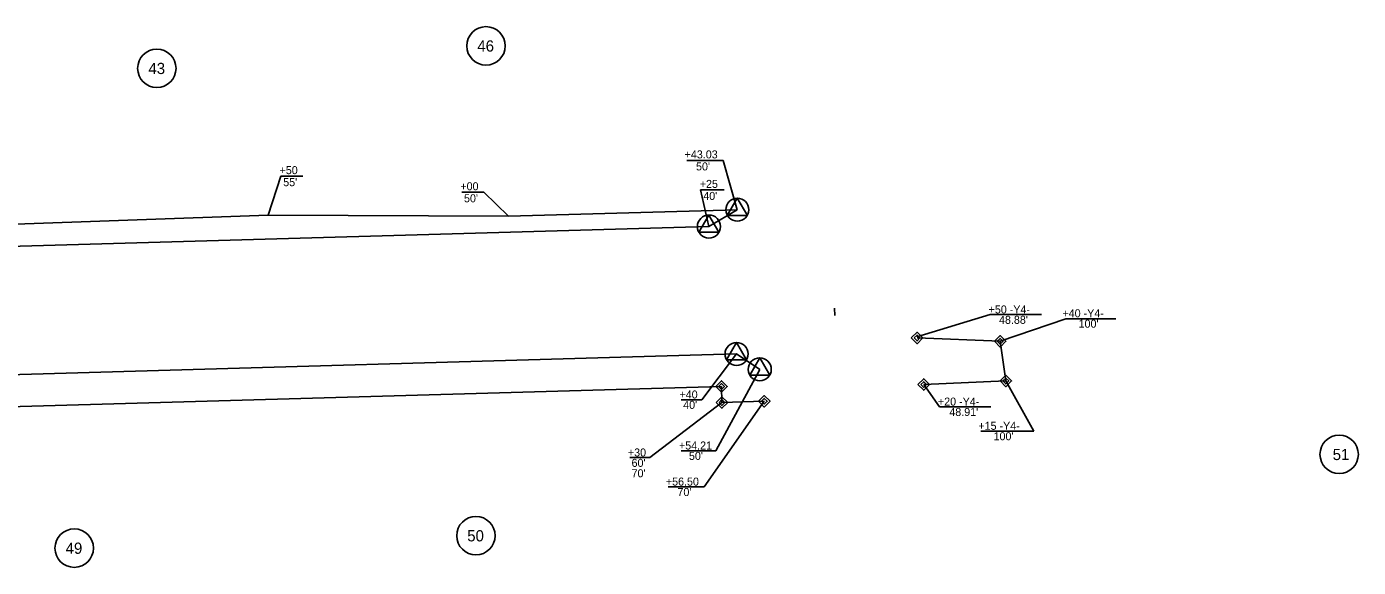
# Model space of a CAD drawing. Extents: x 1756120 to 1760612, y 736784 to 737319.
# Drawn here: x 1759780 to 1760612, y 736882 to 737219 of the extents above; entities that cross this region are included whole.
import ezdxf

# ---------------------------------------------------------------- set-up
doc = ezdxf.new("R2010")
doc.units = 0
for name, color, linetype in [('Prop Easement Construction', 7, 'Continuous'), ('Prop Easement Construction Station Offsets', 7, 'Continuous'), ('Prop Easement Permanent Drainage', 7, 'Continuous'), ('Prop Easement Permanent Drainage Station Offsets', 7, 'Continuous'), ('Prop Easement Permanent Utility', 7, 'Continuous'), ('Prop Easement Permanent Utility Station Offsets', 7, 'Continuous'), ('Prop Easement Temporary Drainage', 7, 'Continuous'), ('Prop Parcel Number CELL', 7, 'Continuous'), ('Prop Parcel Number Text', 7, 'Continuous'), ('Prop ROW Marker CELL', 7, 'Continuous'), ('Prop ROW Permanent Easement CELL', 7, 'Continuous'), ('Prop ROW RW Lines', 7, 'Continuous'), ('Prop ROW Station Offsets', 7, 'Continuous')]:
    doc.layers.add(name, color=color, linetype=linetype)

msp = doc.modelspace()

# ---------------------------------------------------------------- linework, layer by layer
at = {"layer": 'Prop Easement Construction'}
for p, q in [((1760081.35, 737100.66), (1760224.33, 737104.72)), ((1759281.67, 737077.95), (1759931.27, 737101.4)), ((1759931.27, 737101.4), (1760081.35, 737100.66))]:
    msp.add_line(p, q, dxfattribs=at)
at = {"layer": 'Prop Easement Construction Station Offsets'}
for p, q in [((1759939.31, 737125.65), (1759931.27, 737101.4)), ((1759953.03, 737125.65), (1759939.31, 737125.65)), ((1760065.96, 737115.59), (1760052.24, 737115.59)), ((1760065.96, 737115.59), (1760081.35, 737100.66))]:
    msp.add_line(p, q, dxfattribs=at)
at = {"layer": 'Prop Easement Permanent Drainage'}
for p, q in [((1760336.57, 737024.65), (1760388.49, 737022.58)), ((1760392.01, 736997.83), (1760388.49, 737022.58)), ((1760340.72, 736995.59), (1760392.01, 736997.83))]:
    msp.add_line(p, q, dxfattribs=at)
at = {"layer": 'Prop Easement Permanent Drainage Station Offsets'}
for p, q in [((1760336.47, 737025.29), (1760382.24, 737039.22)), ((1760414.34, 737039.22), (1760382.24, 737039.22)), ((1760429.44, 737036.71), (1760388.49, 737022.58)), ((1760460.71, 737036.71), (1760429.44, 737036.71)), ((1760409.51, 736966.46), (1760392.01, 736997.83)), ((1760350.6, 736981.71), (1760340.72, 736995.59)), ((1760382.7, 736981.71), (1760350.6, 736981.71)), ((1760409.51, 736966.46), (1760376.33, 736966.46))]:
    msp.add_line(p, q, dxfattribs=at)
at = {"layer": 'Prop Easement Permanent Utility'}
for p, q in [((1759384.75, 736970.83), (1760214.42, 736994.39)), ((1760214.7, 736984.4), (1760214.42, 736994.39)), ((1760214.7, 736984.4), (1760241.19, 736985.15))]:
    msp.add_line(p, q, dxfattribs=at)
at = {"layer": 'Prop Easement Permanent Utility Station Offsets'}
for p, q in [((1760169.64, 736949.97), (1760214.7, 736984.4)), ((1760203.7, 736931.77), (1760241.19, 736985.15)), ((1760169.64, 736949.97), (1760157.11, 736949.97)), ((1760203.7, 736931.77), (1760181.04, 736931.77))]:
    msp.add_line(p, q, dxfattribs=at)
at = {"layer": 'Prop Easement Temporary Drainage'}
msp.add_line((1760284.96, 737043.18), (1760285.24, 737038.59), dxfattribs=at)
at = {"layer": 'Prop Parcel Number CELL'}
for centre in [(1760067.34, 737206.96), (1759861.77, 737192.94), (1760600.22, 736952.03), (1759810.16, 736893.5), (1760061.06, 736901.26)]:
    msp.add_circle(centre, 12, dxfattribs=at)
at = {"layer": 'Prop ROW Marker CELL'}
for p, q in [((1760224.33, 737104.72), (1760224.33, 737104.72)), ((1760206.58, 737094.21), (1760206.58, 737094.21)), ((1760336.57, 737024.65), (1760336.57, 737024.65)), ((1760388.49, 737022.58), (1760388.49, 737022.58)), ((1760223.85, 737014.67), (1760223.85, 737014.67)), ((1760238.34, 737005.07), (1760238.34, 737005.07)), ((1760392.01, 736997.83), (1760392.01, 736997.83)), ((1760214.42, 736994.39), (1760214.42, 736994.39)), ((1760340.72, 736995.59), (1760340.72, 736995.59)), ((1760214.7, 736984.4), (1760214.7, 736984.4)), ((1760241.19, 736985.15), (1760241.19, 736985.15))]:
    msp.add_line(p, q, dxfattribs=at)
for points in [[(1760218.08, 737101.12), (1760224.33, 737111.92), (1760230.58, 737101.12)], [(1760200.33, 737090.61), (1760206.58, 737101.41), (1760212.83, 737090.61)], [(1760217.6, 737011.07), (1760223.85, 737021.87), (1760230.1, 737011.07)], [(1760232.09, 737001.47), (1760238.34, 737012.27), (1760244.59, 737001.47)]]:
    msp.add_lwpolyline(points, close=True, dxfattribs=at)
for centre in [(1760224.33, 737104.72), (1760206.58, 737094.21), (1760223.85, 737014.67), (1760238.34, 737005.07)]:
    msp.add_circle(centre, 7.2, dxfattribs=at)
at = {"layer": 'Prop ROW Permanent Easement CELL'}
for points in [[(1760332.97, 737024.65), (1760336.57, 737028.25), (1760340.16, 737024.65), (1760336.57, 737021.05)], [(1760334.77, 737024.65), (1760336.57, 737026.45), (1760338.36, 737024.65), (1760336.57, 737022.85)], [(1760384.89, 737022.58), (1760388.49, 737026.18), (1760392.09, 737022.58), (1760388.49, 737018.98)], [(1760386.69, 737022.58), (1760388.49, 737024.38), (1760390.29, 737022.58), (1760388.49, 737020.78)], [(1760210.82, 736994.39), (1760214.42, 736997.99), (1760218.02, 736994.39), (1760214.42, 736990.79)], [(1760337.12, 736995.59), (1760340.72, 736999.19), (1760344.32, 736995.59), (1760340.72, 736991.99)], [(1760338.92, 736995.59), (1760340.72, 736997.39), (1760342.52, 736995.59), (1760340.72, 736993.79)], [(1760388.41, 736997.83), (1760392.01, 737001.43), (1760395.61, 736997.83), (1760392.01, 736994.23)], [(1760390.21, 736997.83), (1760392.01, 736999.63), (1760393.81, 736997.83), (1760392.01, 736996.03)], [(1760212.62, 736994.39), (1760214.42, 736996.19), (1760216.22, 736994.39), (1760214.42, 736992.59)], [(1760237.59, 736985.15), (1760241.19, 736988.75), (1760244.79, 736985.15), (1760241.19, 736981.55)], [(1760211.11, 736984.4), (1760214.71, 736988), (1760218.3, 736984.4), (1760214.71, 736980.8)], [(1760212.9, 736984.4), (1760214.7, 736986.2), (1760216.5, 736984.4), (1760214.7, 736982.6)], [(1760239.39, 736985.15), (1760241.19, 736986.95), (1760242.99, 736985.15), (1760241.19, 736983.35)]]:
    msp.add_lwpolyline(points, close=True, dxfattribs=at)
at = {"layer": 'Prop ROW RW Lines'}
for p, q in [((1760206.58, 737094.21), (1760224.33, 737104.72)), ((1759381.91, 737070.79), (1760206.58, 737094.21)), ((1759384.18, 736990.82), (1760223.85, 737014.67)), ((1760223.85, 737014.67), (1760238.34, 737005.07))]:
    msp.add_line(p, q, dxfattribs=at)
at = {"layer": 'Prop ROW Station Offsets'}
for p, q in [((1760215.47, 737135.48), (1760192.73, 737135.48)), ((1760216.09, 737117.07), (1760201.3, 737117.07)), ((1760202.08, 736985.99), (1760189.15, 736985.99)), ((1760210.9, 736954.3), (1760189.26, 736954.3))]:
    msp.add_line(p, q, dxfattribs=at)
for points in [[(1760215.47, 737135.48), (1760224.33, 737104.72)], [(1760201.3, 737117.07), (1760206.58, 737094.21)], [(1760202.08, 736985.99), (1760223.85, 737014.67)], [(1760210.9, 736954.3), (1760238.34, 737005.07)]]:
    msp.add_lwpolyline(points, dxfattribs=at)

# ---------------------------------------------------------------- texts
at = {"layer": 'Prop Easement Construction Station Offsets'}
for s, p in [('+50', (1759938.42, 737126.9)), ("55'", (1759940.7, 737119.4)), ('+00', (1760051.35, 737116.84)), ("50'", (1760053.63, 737109.34))]:
    msp.add_text(s, height=5, dxfattribs=at).set_placement(p)
at = {"layer": 'Prop Easement Permanent Drainage Station Offsets'}
for s, p in [('+50 -Y4-', (1760381.27, 737039.97)), ("48.88'", (1760387.78, 737033.47)), ('+40 -Y4-', (1760427.41, 737037.58)), ("100'", (1760437.48, 737031.08)), ('+20 -Y4-', (1760349.63, 736982.46)), ("48.91'", (1760356.74, 736975.96)), ('+15 -Y4-', (1760374.89, 736967.33)), ("100'", (1760384.37, 736960.83))]:
    msp.add_text(s, height=5, dxfattribs=at).set_placement(p)
at = {"layer": 'Prop Easement Permanent Utility Station Offsets'}
for s, p in [('+30', (1760155.99, 736950.71)), ("60'", (1760158.28, 736944.21)), ("70'", (1760158.28, 736937.71)), ('+56.50', (1760179.7, 736932.52)), ("70'", (1760186.93, 736926.02))]:
    msp.add_text(s, height=5, dxfattribs=at).set_placement(p)
at = {"layer": 'Prop Parcel Number Text'}
for s, p in [('46', (1760061.95, 737203.41)), ('43', (1759856.51, 737189.38)), ('51', (1760596.19, 736948.47)), ('49', (1759804.8, 736889.95)), ('50', (1760055.64, 736897.71))]:
    msp.add_text(s, height=7, rotation=0.00001, dxfattribs=at).set_placement(p)
at = {"layer": 'Prop ROW Station Offsets'}
for s, p in [('+43.03', (1760191.42, 737136.73)), ("50'", (1760198.54, 737129.23)), ('+25', (1760200.88, 737118.32)), ("40'", (1760203.07, 737110.82)), ('+40', (1760188.21, 736986.91)), ("40'", (1760190.5, 736980.41)), ('+54.21', (1760187.89, 736955.05)), ("50'", (1760194.13, 736948.55))]:
    msp.add_text(s, height=5, dxfattribs=at).set_placement(p)

doc.saveas('drawing.dxf')
